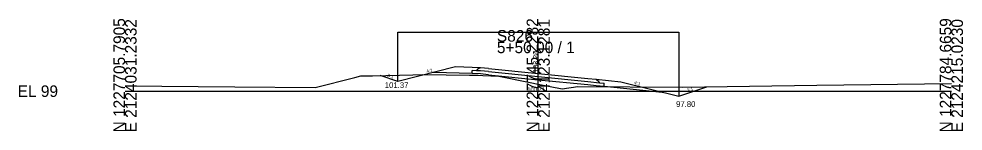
# Model space of a CAD drawing. Extents: x 2118382 to 2118616, y 1213030 to 1222057.
# Drawn here: x 2118381.9 to 2118610.4, y 1216030.1 to 1216057.3 of the extents above; entities that cross this region are included whole.
import ezdxf

# ---------------------------------------------------------------- set-up
doc = ezdxf.new("R2010")
doc.units = 0
for name, color, linetype in [('XS_CELL', 7, 'Continuous'), ('XS_M_DITCH', 7, 'Continuous'), ('XS_P_FINISHED_GRADE', 7, 'Continuous'), ('XS_P_FINISHED_GRADE_ELEV_TX', 7, 'Continuous'), ('XS_P_SUBGRADE_GRANULAR', 7, 'Continuous'), ('XS_P_SUBGRADE_PAVEMENT', 7, 'Continuous'), ('XS_P_TX_DCH', 7, 'Continuous'), ('XS_P_TX_FS_BS', 7, 'Continuous'), ('XS_X_GROUND', 7, 'Continuous'), ('XS_X_GROUND_TX', 7, 'Continuous')]:
    doc.layers.add(name, color=color, linetype=linetype)

msp = doc.modelspace()

# ---------------------------------------------------------------- linework, layer by layer
at = {"layer": 'XS_CELL'}
for p, q in [((2118507.6, 1216039.8), (2118507.6, 1216051.82)), ((2118407.6, 1216039.8), (2118507.6, 1216039.8)), ((2118507.6, 1216039.8), (2118607.6, 1216039.8))]:
    msp.add_line(p, q, dxfattribs=at)
at = {"layer": 'XS_M_DITCH'}
for p, q in [((2118473.6, 1216042.18), (2118473.6, 1216054.09)), ((2118473.6, 1216054.09), (2118541.6, 1216054.09)), ((2118541.6, 1216054.09), (2118541.6, 1216038.6))]:
    msp.add_line(p, q, dxfattribs=at)
at = {"layer": 'XS_P_FINISHED_GRADE'}
for p, q in [((2118487.6, 1216045.67), (2118473.6, 1216042.18)), ((2118493.6, 1216045.49), (2118487.6, 1216045.67)), ((2118495.6, 1216045.29), (2118493.6, 1216045.49)), ((2118495.6, 1216045.29), (2118507.6, 1216044.09)), ((2118473.6, 1216042.18), (2118469.39, 1216043.58)), ((2118507.6, 1216044.09), (2118519.6, 1216042.89)), ((2118519.6, 1216042.89), (2118521.6, 1216042.69)), ((2118521.6, 1216042.69), (2118527.6, 1216042.09)), ((2118527.6, 1216042.09), (2118541.6, 1216038.6)), ((2118541.6, 1216038.6), (2118548.38, 1216040.85))]:
    msp.add_line(p, q, dxfattribs=at)
at = {"layer": 'XS_P_SUBGRADE_GRANULAR'}
for p, q in [((2118491.6, 1216044.05), (2118482.24, 1216044.33)), ((2118491.6, 1216044.05), (2118491.6, 1216044.8)), ((2118492.67, 1216044.77), (2118491.6, 1216044.8)), ((2118493.6, 1216043.99), (2118491.6, 1216044.05)), ((2118495.6, 1216043.79), (2118493.6, 1216043.99)), ((2118495.6, 1216043.79), (2118507.6, 1216042.59)), ((2118507.6, 1216042.59), (2118519.6, 1216041.39)), ((2118519.6, 1216041.39), (2118521.6, 1216041.19)), ((2118521.6, 1216041.19), (2118523.6, 1216040.99)), ((2118522.43, 1216041.86), (2118523.6, 1216041.74)), ((2118523.6, 1216040.99), (2118523.6, 1216041.74)), ((2118523.6, 1216040.99), (2118537.62, 1216039.59))]:
    msp.add_line(p, q, dxfattribs=at)
at = {"layer": 'XS_P_SUBGRADE_PAVEMENT'}
for p, q in [((2118492.87, 1216045.11), (2118492.67, 1216044.77)), ((2118493.6, 1216045.49), (2118492.87, 1216045.11)), ((2118493.6, 1216044.74), (2118492.67, 1216044.77)), ((2118495.6, 1216044.54), (2118493.6, 1216044.74)), ((2118495.6, 1216044.54), (2118507.6, 1216043.34)), ((2118507.6, 1216043.34), (2118519.6, 1216042.14)), ((2118521.6, 1216042.69), (2118522.25, 1216042.17)), ((2118519.6, 1216042.14), (2118522.43, 1216041.86)), ((2118522.25, 1216042.17), (2118522.43, 1216041.86))]:
    msp.add_line(p, q, dxfattribs=at)
at = {"layer": 'XS_X_GROUND'}
for p, q in [((2118453.61, 1216040.69), (2118463.26, 1216043.13)), ((2118463.26, 1216043.13), (2118464.69, 1216043.49)), ((2118464.69, 1216043.49), (2118465, 1216043.49)), ((2118465, 1216043.49), (2118467.48, 1216043.54)), ((2118467.48, 1216043.54), (2118477.26, 1216043.75)), ((2118477.26, 1216043.75), (2118479.66, 1216043.81)), ((2118479.66, 1216043.81), (2118491, 1216043.69)), ((2118491, 1216043.69), (2118492.36, 1216043.67)), ((2118492.36, 1216043.67), (2118493.06, 1216043.65)), ((2118493.06, 1216043.65), (2118494.18, 1216043.6)), ((2118494.18, 1216043.6), (2118498.04, 1216043.44)), ((2118498.04, 1216043.44), (2118505.65, 1216041.91)), ((2118407.6, 1216041.13), (2118434.21, 1216040.85)), ((2118434.21, 1216040.85), (2118453.61, 1216040.69)), ((2118505.65, 1216041.91), (2118507.6, 1216041.51)), ((2118507.6, 1216041.51), (2118513.42, 1216040.33)), ((2118513.42, 1216040.33), (2118517.18, 1216040.95)), ((2118517.18, 1216040.95), (2118542.44, 1216040.77)), ((2118542.44, 1216040.77), (2118575.04, 1216041.25)), ((2118575.04, 1216041.25), (2118607.6, 1216041.64))]:
    msp.add_line(p, q, dxfattribs=at)

# ---------------------------------------------------------------- texts
at = {"layer": 'XS_CELL'}
for s, p in [('N 1227705.7905', (2118407.6, 1216029.8)), ('E 2124031.2332', (2118410.4, 1216029.8)), ('N 1227745.2282', (2118507.6, 1216029.8)), ('E 2124123.1281', (2118510.4, 1216029.8)), ('N 1227784.6659', (2118607.6, 1216029.8)), ('E 2124215.0230', (2118610.4, 1216029.8))]:
    msp.add_text(s, height=2.8, rotation=90, dxfattribs=at).set_placement(p)
for s, p in [('S826', (2118497.6, 1216051.82)), ('5+50.00 / 1', (2118497.6, 1216049.02)), ('EL 99', (2118381.6, 1216038.4))]:
    msp.add_text(s, height=2.8, dxfattribs=at).set_placement(p)
at = {"layer": 'XS_P_FINISHED_GRADE_ELEV_TX'}
msp.add_text(' 103.29', height=1.25, rotation=90, dxfattribs=at).set_placement((2118507.6, 1216043.81))
at = {"layer": 'XS_P_TX_DCH'}
for s, p in [('101.37', (2118470.47, 1216040.56)), ('97.80', (2118540.97, 1216035.97))]:
    msp.add_text(s, height=1.4, dxfattribs=at).set_placement(p)
at = {"layer": 'XS_P_TX_FS_BS'}
for s, rotation, p in [('4:1', 14.0167, (2118480.65, 1216044.19)), ('3:1', 341.5651, (2118471.01, 1216043.32)), ('3:1', 341.5651, (2118471.01, 1216043.32)), ('4:1', 345.9871, (2118530.75, 1216041.52)), ('3:1', 18.4052, (2118543.75, 1216039.58))]:
    msp.add_text(s, height=0.8, rotation=rotation, dxfattribs=at).set_placement(p)
at = {"layer": 'XS_X_GROUND_TX'}
msp.add_text('100.71', height=1, dxfattribs=at).set_placement((2118504.96, 1216039.72))

doc.saveas('drawing.dxf')
